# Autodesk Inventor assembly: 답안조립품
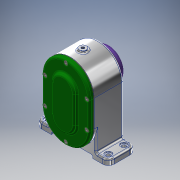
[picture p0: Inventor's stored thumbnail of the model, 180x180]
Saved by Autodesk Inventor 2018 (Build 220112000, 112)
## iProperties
Created: 2021-05
Part Number: 답안조립품
Material: 일반
Document SubType Name: Assembly
Designer: Admin
Author: Admin
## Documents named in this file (19)
- C:\Users\Admin\Desktop\710509V1011\답안조립품.iam
- C:\Users\Admin\Desktop\710509V1011\본체.ipt
- C:\Users\Admin\Desktop\710509V1011\축 A.ipt
- C:\Users\Admin\Desktop\710509V1011\베어링 6001.ipt
- 베어링 6001.ipt
- C:\Users\Admin\Desktop\710509V1011\베어링 6002.ipt
- 베어링 6002.ipt
- C:\Users\Admin\Desktop\710509V1011\칼라.ipt
- C:\Users\Admin\Desktop\710509V1011\축 B.ipt
- C:\Users\Admin\Desktop\710509V1011\스퍼기어 A.ipt
- C:\Users\Admin\Desktop\710509V1011\키 5 x 5 x 12.ipt
- C:\Users\Admin\Desktop\710509V1011\키 4 x 4 x 12.ipt
- C:\Users\Admin\Desktop\710509V1011\스퍼기어 B.ipt
- C:\Users\Admin\Desktop\710509V1011\개스킷 A.ipt
- C:\Users\Admin\Desktop\710509V1011\개스킷 B.ipt
- C:\Users\Admin\Desktop\710509V1011\커버 A.ipt
- C:\Users\Admin\Desktop\710509V1011\커버 B.ipt
- C:\Users\Admin\Desktop\710509V1011\볼트 M4.ipt
- C:\Users\Admin\Desktop\710509V1011\오일 실 12 22 7.ipt
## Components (2 placed, 2 different names)
1. 개스킷 A:1
2. 개스킷 B:1
